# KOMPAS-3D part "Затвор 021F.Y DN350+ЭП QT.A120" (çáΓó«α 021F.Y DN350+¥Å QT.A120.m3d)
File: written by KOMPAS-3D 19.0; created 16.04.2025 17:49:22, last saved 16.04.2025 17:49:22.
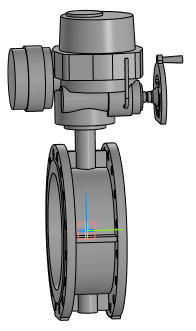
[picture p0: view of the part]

Document properties: Полное имя файла: Затвор 021F.Y DN350+ЭП QT.A120.a3d

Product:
- Part/product: Затвор 021F.Y DN350+ЭП QT.A120
    Масса: 227.718

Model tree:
1. Операция без истории:1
